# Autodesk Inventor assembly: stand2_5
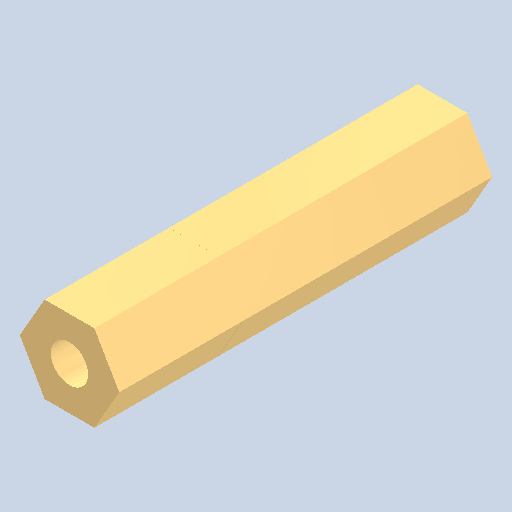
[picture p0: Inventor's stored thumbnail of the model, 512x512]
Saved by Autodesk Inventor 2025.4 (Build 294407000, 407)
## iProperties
Created: 2026-09
Part Number: stand2_5
Document SubType Name: Assembly
Designer: AdminForWorker
Title: stanofff v1
Author: AdminForWorker
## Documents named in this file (3)
- c:\worker\convert-fusion-r05-cosv3\tmp\job-1\19\temp\files\ca3d996b-dda0-445d-8bee-12a194174ca8\stanofff v1_4.iam
- c:\worker\convert-fusion-r05-cosv3\tmp\job-1\19\temp\files\ca3d996b-dda0-445d-8bee-12a194174ca8\M3-10 v1 (2).ipt
- c:\worker\convert-fusion-r05-cosv3\tmp\job-1\19\temp\files\ca3d996b-dda0-445d-8bee-12a194174ca8\M3-20 v1.ipt
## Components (2 placed, 2 different names)
1. M3-10 v1 (2):1
2. M3-20 v1:1
